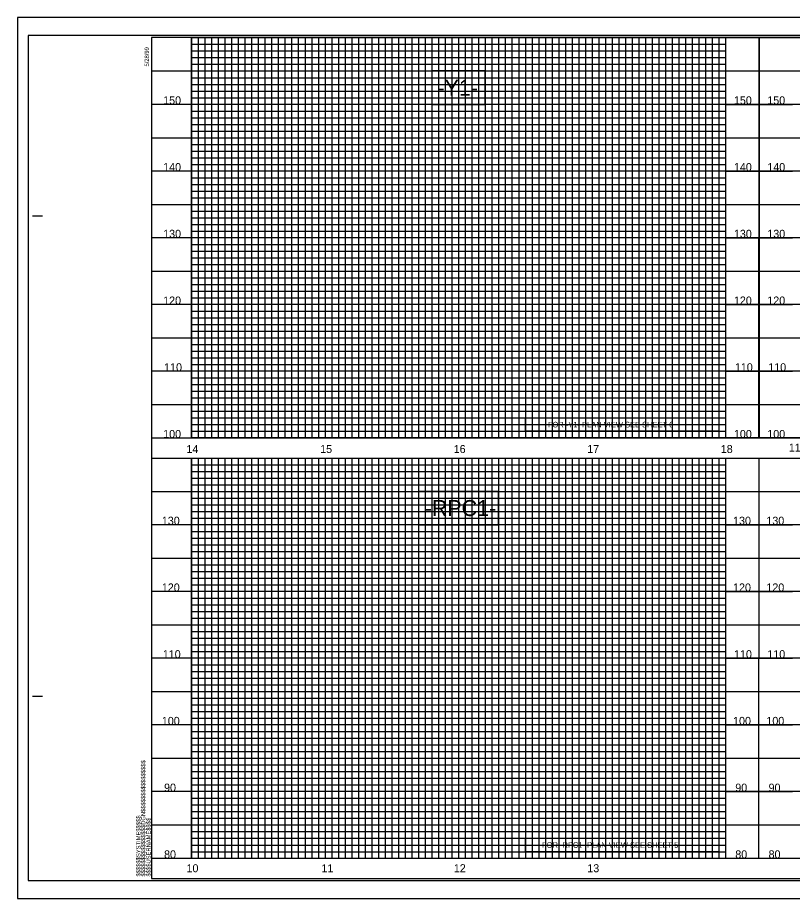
# Model space of a CAD drawing. Extents: x 270 to 1290, y -4845 to -4185.
# Drawn here: x 270 to 850, y -4845 to -4185 of the extents above; entities that cross this region are included whole.
import ezdxf

# ---------------------------------------------------------------- set-up
doc = ezdxf.new("R2010")
doc.units = 0
for name, color, linetype in [('Exist Vertical Profile Horizontal Axis Label Major', 7, 'Continuous'), ('Exist Vertical Profile Vertical Axis Label', 7, 'Continuous'), ('Prop Grid Mask', 7, 'Continuous'), ('Prop PFL Text', 7, 'Continuous'), ('Scratch_Level_1', 7, 'Continuous'), ('Sheet Cutting Line CELL', 7, 'Continuous'), ('Sheet Layout Profile Border Port 1', 7, 'Continuous'), ('Sheet Layout Profile Border Port 2', 7, 'Continuous'), ('Sheet Plot Border Inside CELL', 7, 'Continuous'), ('Sheet Plot Border Outside CELL', 7, 'Continuous'), ('Sheet Profile CELL', 7, 'Continuous'), ('Sheet Profile Grid Major CELL', 7, 'Continuous'), ('Sheet Profile Grid Middle CELL', 7, 'Continuous'), ('Sheet Profile Grid Minor CELL', 7, 'Continuous')]:
    doc.layers.add(name, color=color, linetype=linetype)

msp = doc.modelspace()

# ---------------------------------------------------------------- linework, layer by layer
at = {"layer": 'Exist Vertical Profile Vertical Axis Label'}
for points in [[(650, -4484.75), (795, -4484.75), (795, -4494.75), (650, -4494.75)], [(650, -4799.75), (795, -4799.75), (795, -4809.75), (650, -4809.75)]]:
    msp.add_lwpolyline(points, close=True, dxfattribs=at)
at = {"layer": 'Prop Grid Mask'}
for points in [[(580, -4249.75), (620, -4249.75), (620, -4224.75), (580, -4224.75)], [(650, -4484.75), (795, -4484.75), (795, -4494.75), (650, -4494.75)], [(570, -4564.75), (630, -4564.75), (630, -4539.75), (570, -4539.75)], [(650, -4799.75), (795, -4799.75), (795, -4809.75), (650, -4809.75)]]:
    msp.add_lwpolyline(points, close=True, dxfattribs=at)
at = {"layer": 'Prop PFL Text'}
for points in [[(580, -4249.75), (620, -4249.75), (620, -4224.75), (580, -4224.75)], [(570, -4564.75), (630, -4564.75), (630, -4539.75), (570, -4539.75)]]:
    msp.add_lwpolyline(points, close=True, dxfattribs=at)
at = {"layer": 'Scratch_Level_1'}
for points in [[(400, -4199.75), (800, -4199.75), (800, -4499.75), (400, -4499.75)], [(400, -4514.75), (800, -4514.75), (800, -4814.75), (400, -4814.75)]]:
    msp.add_lwpolyline(points, close=True, dxfattribs=at)
at = {"layer": 'Sheet Cutting Line CELL'}
for p, q in [((1289.8, -4184.75), (269.8, -4184.75)), ((269.8, -4184.75), (269.8, -4844.75)), ((269.8, -4844.75), (1289.8, -4844.75))]:
    msp.add_line(p, q, dxfattribs=at)
at = {"layer": 'Sheet Layout Profile Border Port 1'}
msp.add_lwpolyline([(400, -4199.75), (1149.97, -4199.75), (1149.97, -4319.63), (1240, -4319.75), (1240, -4499.75), (400, -4499.75)], close=True, dxfattribs=at)
at = {"layer": 'Sheet Layout Profile Border Port 2'}
msp.add_lwpolyline([(400, -4514.75), (1240, -4514.75), (1240, -4814.75), (400, -4814.75)], close=True, dxfattribs=at)
at = {"layer": 'Sheet Plot Border Inside CELL'}
msp.add_lwpolyline([(277.6, -4831.28), (1277.5, -4831.28), (1277.5, -4198.22), (277.6, -4198.22)], close=True, dxfattribs=at)
at = {"layer": 'Sheet Plot Border Outside CELL'}
msp.add_lwpolyline([(269.8, -4844.75), (1289.8, -4844.75), (1289.8, -4184.75), (269.8, -4184.75)], close=True, dxfattribs=at)
at = {"layer": 'Sheet Profile CELL'}
for p, q in [((280.9, -4333.25), (288.4, -4333.25)), ((370, -4499.75), (1270, -4499.75)), ((370, -4514.75), (1270, -4514.75)), ((280.9, -4693.25), (288.4, -4693.25)), ((1270, -4814.75), (370, -4814.75)), ((370, -4829.75), (1270, -4829.75)), ((370, -4829.75), (370, -4829.75)), ((370, -4829.75), (370, -4829.75)), ((370, -4829.75), (370, -4829.75)), ((370, -4829.75), (370, -4829.75)), ((370, -4829.75), (370, -4829.75)), ((370, -4829.75), (370, -4829.75)), ((370, -4829.75), (370, -4829.75))]:
    msp.add_line(p, q, dxfattribs=at)
msp.add_lwpolyline([(1270, -4199.75), (370, -4199.75), (370, -4829.75), (1270, -4829.75)], close=True, dxfattribs=at)
msp.add_lwpolyline([(392.5, -4829.75), (392.5, -4829.75)], dxfattribs=at)
at = {"layer": 'Sheet Profile Grid Major CELL'}
for p, q in [((400, -4199.75), (400, -4499.75)), ((425, -4199.75), (425, -4499.75)), ((450, -4199.75), (450, -4499.75)), ((475, -4199.75), (475, -4499.75)), ((500, -4199.75), (500, -4499.75)), ((525, -4199.75), (525, -4499.75)), ((550, -4199.75), (550, -4499.75)), ((575, -4199.75), (575, -4499.75)), ((600, -4199.75), (600, -4499.75)), ((625, -4199.75), (625, -4499.75)), ((650, -4199.75), (650, -4499.75)), ((675, -4199.75), (675, -4499.75)), ((700, -4199.75), (700, -4499.75)), ((725, -4199.75), (725, -4499.75)), ((750, -4199.75), (750, -4499.75)), ((775, -4199.75), (775, -4499.75)), ((800, -4199.75), (800, -4499.75)), ((824.93, -4499.75), (825.2, -4199.75)), ((825, -4199.75), (825, -4499.75)), ((370, -4224.75), (1150, -4224.75)), ((800, -4224.75), (850, -4224.75)), ((1150, -4249.75), (370, -4249.75)), ((800, -4249.75), (850, -4249.75)), ((370, -4274.75), (1150, -4274.75)), ((800, -4274.75), (850, -4274.75)), ((1150, -4299.75), (370, -4299.75)), ((800, -4299.75), (850, -4299.75)), ((370, -4324.75), (1270, -4324.75)), ((800, -4324.75), (850, -4324.75)), ((1270, -4349.75), (370, -4349.75)), ((800, -4349.75), (850, -4349.75)), ((370, -4374.75), (1270, -4374.75)), ((800, -4374.75), (850, -4374.75)), ((1270, -4399.75), (370, -4399.75)), ((800, -4399.75), (850, -4399.75)), ((370, -4424.75), (1270, -4424.75)), ((800, -4424.75), (850, -4424.75)), ((1270, -4449.75), (370, -4449.75)), ((800, -4449.75), (850, -4449.75)), ((370, -4474.75), (1270, -4474.75)), ((800, -4474.75), (849.91, -4474.75)), ((400, -4514.75), (400, -4814.75)), ((425, -4514.75), (425, -4814.75)), ((450, -4514.75), (450, -4814.75)), ((475, -4514.75), (475, -4814.75)), ((500, -4514.75), (500, -4814.75)), ((525, -4514.75), (525, -4814.75)), ((550, -4514.75), (550, -4814.75)), ((575, -4514.75), (575, -4814.75)), ((600, -4514.75), (600, -4814.75)), ((625, -4514.75), (625, -4814.75)), ((650, -4514.75), (650, -4814.75)), ((675, -4514.75), (675, -4814.75)), ((700, -4514.75), (700, -4814.75)), ((725, -4514.75), (725, -4814.75)), ((750, -4514.75), (750, -4814.75)), ((775, -4514.75), (775, -4814.75)), ((800, -4514.75), (800, -4814.75)), ((824.93, -4814.75), (825.2, -4514.75)), ((370, -4539.75), (1270, -4539.75)), ((800, -4539.75), (850, -4539.75)), ((1270, -4564.75), (370, -4564.75)), ((800, -4564.75), (850, -4564.75)), ((370, -4589.75), (1270, -4589.75)), ((800, -4589.75), (850, -4589.75)), ((1270, -4614.75), (370, -4614.75)), ((800, -4614.75), (850, -4614.75)), ((370, -4639.75), (1270, -4639.75)), ((800, -4639.75), (850, -4639.75)), ((1270, -4664.75), (370, -4664.75)), ((800, -4664.75), (850, -4664.75)), ((370, -4689.75), (1270, -4689.75)), ((800, -4689.75), (850, -4689.75)), ((1270, -4714.75), (370, -4714.75)), ((800, -4714.75), (850, -4714.75)), ((370, -4739.75), (1270, -4739.75)), ((800, -4739.75), (850, -4739.75)), ((1270, -4764.75), (370, -4764.75)), ((800, -4764.75), (850, -4764.75)), ((370, -4789.75), (1270, -4789.75)), ((800, -4789.75), (849.91, -4789.75))]:
    msp.add_line(p, q, dxfattribs=at)
at = {"layer": 'Sheet Profile Grid Middle CELL'}
for p, q in [((400, -4204.75), (800, -4204.75)), ((400, -4209.75), (800, -4209.75)), ((400, -4214.75), (800, -4214.75)), ((400, -4219.75), (800, -4219.75)), ((400, -4229.75), (800, -4229.75)), ((400, -4234.75), (800, -4234.75)), ((400, -4239.75), (800, -4239.75)), ((400, -4244.75), (800, -4244.75)), ((400, -4254.75), (800, -4254.75)), ((400, -4259.75), (800, -4259.75)), ((400, -4264.75), (800, -4264.75)), ((400, -4269.75), (800, -4269.75)), ((400, -4279.75), (800, -4279.75)), ((400, -4284.75), (800, -4284.75)), ((400, -4289.75), (800, -4289.75)), ((400, -4294.75), (800, -4294.75)), ((400, -4304.75), (800, -4304.75)), ((400, -4309.75), (800, -4309.75)), ((400, -4314.75), (800, -4314.75)), ((400, -4319.75), (800, -4319.75)), ((400, -4329.75), (800, -4329.75)), ((400, -4334.75), (800, -4334.75)), ((400, -4339.75), (800, -4339.75)), ((400, -4344.75), (800, -4344.75)), ((400, -4354.75), (800, -4354.75)), ((400, -4359.75), (800, -4359.75)), ((400, -4364.75), (800, -4364.75)), ((400, -4369.75), (800, -4369.75)), ((400, -4379.75), (800, -4379.75)), ((400, -4384.75), (800, -4384.75)), ((400, -4389.75), (800, -4389.75)), ((400, -4394.75), (800, -4394.75)), ((400, -4404.75), (800, -4404.75)), ((400, -4409.75), (800, -4409.75)), ((400, -4414.75), (800, -4414.75)), ((400, -4419.75), (800, -4419.75)), ((400, -4429.75), (800, -4429.75)), ((400, -4434.75), (800, -4434.75)), ((400, -4439.75), (800, -4439.75)), ((400, -4444.75), (800, -4444.75)), ((400, -4454.75), (800, -4454.75)), ((400, -4459.75), (800, -4459.75)), ((400, -4464.75), (800, -4464.75)), ((400, -4469.75), (800, -4469.75)), ((400, -4479.75), (800, -4479.75)), ((400, -4484.75), (800, -4484.75)), ((400, -4489.75), (800, -4489.75)), ((400, -4494.75), (800, -4494.75)), ((400, -4519.75), (800, -4519.75)), ((400, -4524.75), (800, -4524.75)), ((400, -4529.75), (800, -4529.75)), ((400, -4534.75), (800, -4534.75)), ((400, -4544.75), (800, -4544.75)), ((400, -4549.75), (800, -4549.75)), ((400, -4554.75), (800, -4554.75)), ((400, -4559.75), (800, -4559.75)), ((400, -4569.75), (800, -4569.75)), ((400, -4574.75), (800, -4574.75)), ((400, -4579.75), (800, -4579.75)), ((400, -4584.75), (800, -4584.75)), ((400, -4594.75), (800, -4594.75)), ((400, -4599.75), (800, -4599.75)), ((400, -4604.75), (800, -4604.75)), ((400, -4609.75), (800, -4609.75)), ((400, -4619.75), (800, -4619.75)), ((400, -4624.75), (800, -4624.75)), ((400, -4629.75), (800, -4629.75)), ((400, -4634.75), (800, -4634.75)), ((400, -4644.75), (800, -4644.75)), ((400, -4649.75), (800, -4649.75)), ((400, -4654.75), (800, -4654.75)), ((400, -4659.75), (800, -4659.75)), ((400, -4669.75), (800, -4669.75)), ((400, -4674.75), (800, -4674.75)), ((400, -4679.75), (800, -4679.75)), ((400, -4684.75), (800, -4684.75)), ((400, -4694.75), (800, -4694.75)), ((400, -4699.75), (800, -4699.75)), ((400, -4704.75), (800, -4704.75)), ((400, -4709.75), (800, -4709.75)), ((400, -4719.75), (800, -4719.75)), ((400, -4724.75), (800, -4724.75)), ((400, -4729.75), (800, -4729.75)), ((400, -4734.75), (800, -4734.75)), ((400, -4744.75), (800, -4744.75)), ((400, -4749.75), (800, -4749.75)), ((400, -4754.75), (800, -4754.75)), ((400, -4759.75), (800, -4759.75)), ((400, -4769.75), (800, -4769.75)), ((400, -4774.75), (800, -4774.75)), ((400, -4779.75), (800, -4779.75)), ((400, -4784.75), (800, -4784.75)), ((400, -4794.75), (800, -4794.75)), ((400, -4799.75), (800, -4799.75)), ((400, -4804.75), (800, -4804.75)), ((400, -4809.75), (800, -4809.75))]:
    msp.add_line(p, q, dxfattribs=at)
at = {"layer": 'Sheet Profile Grid Minor CELL'}
for p, q in [((405, -4199.75), (405, -4499.75)), ((410, -4199.75), (410, -4499.75)), ((415, -4199.75), (415, -4499.75)), ((420, -4199.75), (420, -4499.75)), ((430, -4199.75), (430, -4499.75)), ((435, -4199.75), (435, -4499.75)), ((440, -4199.75), (440, -4499.75)), ((445, -4199.75), (445, -4499.75)), ((455, -4199.75), (455, -4499.75)), ((460, -4199.75), (460, -4499.75)), ((465, -4199.75), (465, -4499.75)), ((470, -4199.75), (470, -4499.75)), ((480, -4199.75), (480, -4499.75)), ((485, -4199.75), (485, -4499.75)), ((490, -4199.75), (490, -4499.75)), ((495, -4199.75), (495, -4499.75)), ((505, -4199.75), (505, -4499.75)), ((510, -4199.75), (510, -4499.75)), ((515, -4199.75), (515, -4499.75)), ((520, -4199.75), (520, -4499.75)), ((530, -4199.75), (530, -4499.75)), ((535, -4199.75), (535, -4499.75)), ((540, -4199.75), (540, -4499.75)), ((545, -4199.75), (545, -4499.75)), ((555, -4199.75), (555, -4499.75)), ((560, -4199.75), (560, -4499.75)), ((565, -4199.75), (565, -4499.75)), ((570, -4199.75), (570, -4499.75)), ((580, -4199.75), (580, -4499.75)), ((585, -4199.75), (585, -4499.75)), ((590, -4199.75), (590, -4499.75)), ((595, -4199.75), (595, -4499.75)), ((605, -4199.75), (605, -4499.75)), ((610, -4199.75), (610, -4499.75)), ((615, -4199.75), (615, -4499.75)), ((620, -4199.75), (620, -4499.75)), ((630, -4199.75), (630, -4499.75)), ((635, -4199.75), (635, -4499.75)), ((640, -4199.75), (640, -4499.75)), ((645, -4199.75), (645, -4499.75)), ((655, -4199.75), (655, -4499.75)), ((660, -4199.75), (660, -4499.75)), ((665, -4199.75), (665, -4499.75)), ((670, -4199.75), (670, -4499.75)), ((680, -4199.75), (680, -4499.75)), ((685, -4199.75), (685, -4499.75)), ((690, -4199.75), (690, -4499.75)), ((695, -4199.75), (695, -4499.75)), ((705, -4199.75), (705, -4499.75)), ((710, -4199.75), (710, -4499.75)), ((715, -4199.75), (715, -4499.75)), ((720, -4199.75), (720, -4499.75)), ((730, -4199.75), (730, -4499.75)), ((735, -4199.75), (735, -4499.75)), ((740, -4199.75), (740, -4499.75)), ((745, -4199.75), (745, -4499.75)), ((755, -4199.75), (755, -4499.75)), ((760, -4199.75), (760, -4499.75)), ((765, -4199.75), (765, -4499.75)), ((770, -4199.75), (770, -4499.75)), ((780, -4199.75), (780, -4499.75)), ((785, -4199.75), (785, -4499.75)), ((790, -4199.75), (790, -4499.75)), ((795, -4199.75), (795, -4499.75)), ((400, -4205.75), (400, -4205.75)), ((400, -4520.75), (400, -4520.75)), ((405, -4514.75), (405, -4814.75)), ((410, -4514.75), (410, -4814.75)), ((415, -4514.75), (415, -4814.75)), ((420, -4514.75), (420, -4814.75)), ((430, -4514.75), (430, -4814.75)), ((435, -4514.75), (435, -4814.75)), ((440, -4514.75), (440, -4814.75)), ((445, -4514.75), (445, -4814.75)), ((455, -4514.75), (455, -4814.75)), ((460, -4514.75), (460, -4814.75)), ((465, -4514.75), (465, -4814.75)), ((470, -4514.75), (470, -4814.75)), ((480, -4514.75), (480, -4814.75)), ((485, -4514.75), (485, -4814.75)), ((490, -4514.75), (490, -4814.75)), ((495, -4514.75), (495, -4814.75)), ((505, -4514.75), (505, -4814.75)), ((510, -4514.75), (510, -4814.75)), ((515, -4514.75), (515, -4814.75)), ((520, -4514.75), (520, -4814.75)), ((530, -4514.75), (530, -4814.75)), ((535, -4514.75), (535, -4814.75)), ((540, -4514.75), (540, -4814.75)), ((545, -4514.75), (545, -4814.75)), ((555, -4514.75), (555, -4814.75)), ((560, -4514.75), (560, -4814.75)), ((565, -4514.75), (565, -4814.75)), ((570, -4514.75), (570, -4814.75)), ((580, -4514.75), (580, -4814.75)), ((585, -4514.75), (585, -4814.75)), ((590, -4514.75), (590, -4814.75)), ((595, -4514.75), (595, -4814.75)), ((605, -4514.75), (605, -4814.75)), ((610, -4514.75), (610, -4814.75)), ((615, -4514.75), (615, -4814.75)), ((620, -4514.75), (620, -4814.75)), ((630, -4514.75), (630, -4814.75)), ((635, -4514.75), (635, -4814.75)), ((640, -4514.75), (640, -4814.75)), ((645, -4514.75), (645, -4814.75)), ((655, -4514.75), (655, -4814.75)), ((660, -4514.75), (660, -4814.75)), ((665, -4514.75), (665, -4814.75)), ((670, -4514.75), (670, -4814.75)), ((680, -4514.75), (680, -4814.75)), ((685, -4514.75), (685, -4814.75)), ((690, -4514.75), (690, -4814.75)), ((695, -4514.75), (695, -4814.75)), ((705, -4514.75), (705, -4814.75)), ((710, -4514.75), (710, -4814.75)), ((715, -4514.75), (715, -4814.75)), ((720, -4514.75), (720, -4814.75)), ((730, -4514.75), (730, -4814.75)), ((735, -4514.75), (735, -4814.75)), ((740, -4514.75), (740, -4814.75)), ((745, -4514.75), (745, -4814.75)), ((755, -4514.75), (755, -4814.75)), ((760, -4514.75), (760, -4814.75)), ((765, -4514.75), (765, -4814.75)), ((770, -4514.75), (770, -4814.75)), ((780, -4514.75), (780, -4814.75)), ((785, -4514.75), (785, -4814.75)), ((790, -4514.75), (790, -4814.75)), ((795, -4514.75), (795, -4814.75))]:
    msp.add_line(p, q, dxfattribs=at)

# ---------------------------------------------------------------- texts
at = {"layer": 'Exist Vertical Profile Horizontal Axis Label Major'}
for s, p in [('14', (396.22, -4511.03)), ('15', (496.35, -4511.03)), ('16', (596.35, -4511.03)), ('17', (696.32, -4511.03)), ('18', (796.35, -4511.03)), ('11', (847.3, -4509.93)), ('10', (396.27, -4825.16)), ('11', (497.32, -4825.16)), ('12', (596.44, -4825.16)), ('13', (696.4, -4825.16))]:
    msp.add_text(s, height=6, dxfattribs=at).set_placement(p)
at = {"layer": 'Exist Vertical Profile Vertical Axis Label'}
for s, p in [('150', (378.79, -4249.75)), ('150', (806.19, -4249.75)), ('150', (831.19, -4249.75)), ('140', (378.79, -4299.75)), ('140', (806.19, -4299.75)), ('140', (831.19, -4299.75)), ('130', (378.79, -4349.75)), ('130', (806.19, -4349.75)), ('130', (831.19, -4349.75)), ('120', (378.79, -4399.75)), ('120', (806.19, -4399.75)), ('120', (831.19, -4399.75)), ('110', (379.51, -4449.75)), ('110', (806.9, -4449.75)), ('110', (831.9, -4449.75)), ('100', (378.79, -4499.75)), ('100', (806.19, -4499.75)), ('100', (831.19, -4499.75)), ('130', (377.8, -4564.75)), ('130', (805.56, -4564.75)), ('130', (830.49, -4564.75)), ('120', (377.8, -4614.75)), ('120', (805.56, -4614.75)), ('120', (830.49, -4614.75)), ('110', (378.52, -4664.75)), ('110', (806.28, -4664.75)), ('110', (831.21, -4664.75)), ('100', (377.8, -4714.75)), ('100', (805.56, -4714.75)), ('100', (830.49, -4714.75)), ('90', (379.46, -4764.75)), ('90', (807.21, -4764.75)), ('90', (832.15, -4764.75)), ('80', (379.46, -4814.75)), ('80', (807.21, -4814.75)), ('80', (832.15, -4814.75))]:
    msp.add_text(s, height=6, dxfattribs=at).set_placement(p)
at = {"layer": 'Prop PFL Text'}
for s, height, p in [('-Y1-', 12, (584.18, -4243.25)), ('FOR -Y1- PLAN VIEW SEE SHEET 6', 4.2, (666.88, -4491.85)), ('-RPC1-', 12, (574.62, -4558.25)), ('FOR -RPC1- PLAN VIEW SEE SHEET 5', 4.2, (662.53, -4806.85))]:
    msp.add_text(s, height=height, dxfattribs=at).set_placement(p)
at = {"layer": 'Sheet Profile CELL'}
for s, p in [('5/28/99', (368.06, -4221.4)), ('$$$$$$$$$$$$$$$$DGN$$$$$$$$$$$$$$$$', (365.42, -4828.32)), ('$$$$$$SYSTIME$$$$$', (361.79, -4828.32)), ('$$$$USERNAME$$$$', (369.36, -4828.32))]:
    msp.add_text(s, height=3.15, rotation=90, dxfattribs=at).set_placement(p)

doc.saveas('drawing.dxf')
